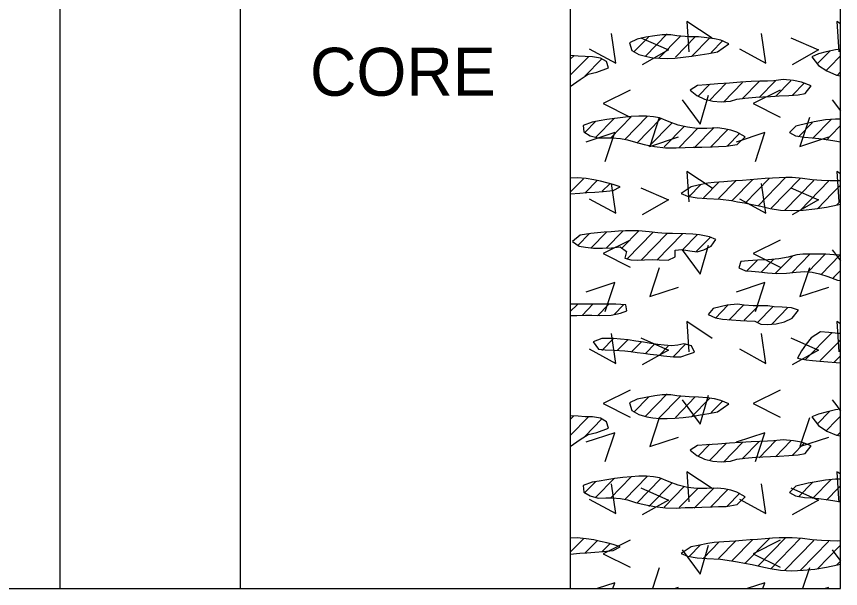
# Model space of a CAD drawing. Extents: x 0 to 0.83, y -0.65 to 1.27.
# Drawn here: x 0.719 to 0.8333, y -0.6457 to -0.5663 of the extents above; entities that cross this region are included whole.
import ezdxf

# ---------------------------------------------------------------- set-up
doc = ezdxf.new("R2010")
doc.units = 0

msp = doc.modelspace()

# ---------------------------------------------------------------- linework, layer by layer
for points in [[(0.725, 1.22083), (0.725, -0.64575)], [(0.75, 1.22083), (0.75, -0.64575)], [(0.75, 1.22083), (0.75, -0.64575)], [(0.79583, 1.22083), (0.79583, -0.64575)], [(0.725, 1.20833), (0.725, -0.64575)], [(0.83333, -0.64575), (0.83333, 1.13365)], [(0.81551, -0.56934), (0.81201, -0.56703), (0.81226, -0.57121)], [(0.83333, -0.56735), (0.83284, -0.56703), (0.83309, -0.57121)], [(0.79847, -0.57082), (0.80215, -0.57282), (0.80153, -0.5687)], [(0.80465, -0.57124), (0.80667, -0.56917)], [(0.80562, -0.56928), (0.80946, -0.57096), (0.80581, -0.57302)], [(0.80626, -0.57181), (0.80928, -0.56871)], [(0.80809, -0.57214), (0.81111, -0.56905)], [(0.81041, -0.57198), (0.81318, -0.56915)], [(0.81264, -0.5719), (0.81518, -0.5693)], [(0.8193, -0.57082), (0.82299, -0.57282), (0.82236, -0.5687)], [(0.82645, -0.56928), (0.83029, -0.57096), (0.82664, -0.57302)], [(0.81536, -0.57133), (0.81699, -0.56967)], [(0.8301, -0.57291), (0.83184, -0.57112)], [(0.7963, -0.57179), (0.79583, -0.57227)], [(0.79834, -0.57192), (0.79583, -0.57449)], [(0.79786, -0.57462), (0.80023, -0.57219)], [(0.83131, -0.57388), (0.83181, -0.57337), (0.83333, -0.5718)], [(0.83285, -0.57451), (0.83333, -0.57402)], [(0.81519, -0.57572), (0.81354, -0.57742)], [(0.81514, -0.57798), (0.81748, -0.57559)], [(0.81709, -0.5782), (0.81974, -0.57548)], [(0.8197, -0.57775), (0.82203, -0.57535)], [(0.82202, -0.57758), (0.8243, -0.57524)], [(0.82431, -0.57745), (0.82644, -0.57526)], [(0.82663, -0.57728), (0.82834, -0.57553)], [(0.80412, -0.57653), (0.80038, -0.57841), (0.80412, -0.58028)], [(0.81134, -0.57788), (0.81384, -0.58125), (0.81503, -0.57725)], [(0.82496, -0.57653), (0.82121, -0.57841), (0.82496, -0.58028)], [(0.83217, -0.57788), (0.83333, -0.57944)], [(0.79938, -0.58087), (0.79786, -0.58242)], [(0.79933, -0.58313), (0.80195, -0.58044)], [(0.80142, -0.5832), (0.8043, -0.58025)], [(0.80653, -0.58017), (0.8034, -0.58339)], [(0.80506, -0.58389), (0.8084, -0.58047)], [(0.80818, -0.58037), (0.80687, -0.58437), (0.81087, -0.58305)], [(0.82901, -0.58037), (0.8277, -0.58437), (0.8317, -0.58305)], [(0.83203, -0.58061), (0.82949, -0.58321)], [(0.80997, -0.58107), (0.80675, -0.58438)], [(0.81164, -0.58158), (0.80884, -0.58444)], [(0.81353, -0.58185), (0.81094, -0.58451)], [(0.81303, -0.58457), (0.81579, -0.58175)], [(0.81534, -0.58442), (0.81768, -0.58202)], [(0.82751, -0.58302), (0.82945, -0.58103)], [(0.83138, -0.58348), (0.83201, -0.58284), (0.83333, -0.58148)], [(0.80069, -0.58645), (0.802, -0.58245), (0.798, -0.58376)], [(0.8176, -0.58431), (0.81934, -0.58253)], [(0.82152, -0.58645), (0.82284, -0.58245), (0.81884, -0.58376)], [(0.83333, -0.5837), (0.83333, -0.58369)], [(0.79765, -0.58885), (0.79583, -0.59071)], [(0.81551, -0.59017), (0.81201, -0.58786), (0.81226, -0.59205)], [(0.82004, -0.59229), (0.82346, -0.58878)], [(0.82569, -0.5887), (0.82184, -0.59265)], [(0.82775, -0.5888), (0.8237, -0.59295)], [(0.83333, -0.58818), (0.83284, -0.58786), (0.83309, -0.59205)], [(0.7996, -0.58906), (0.79786, -0.59084)], [(0.79847, -0.59165), (0.80215, -0.59365), (0.80153, -0.58953)], [(0.8013, -0.58954), (0.80027, -0.59059)], [(0.81392, -0.5897), (0.81235, -0.5913)], [(0.8143, -0.59152), (0.8165, -0.58927)], [(0.8164, -0.59159), (0.81879, -0.58914)], [(0.81829, -0.59187), (0.82114, -0.58894)], [(0.8193, -0.59165), (0.82299, -0.59365), (0.82236, -0.58953)], [(0.82964, -0.58908), (0.82557, -0.59326)], [(0.83173, -0.58915), (0.82774, -0.59324)], [(0.83333, -0.58973), (0.83218, -0.59091), (0.83012, -0.59302)], [(0.80562, -0.59011), (0.80946, -0.59179), (0.80581, -0.59385)], [(0.82645, -0.59011), (0.83029, -0.59179), (0.82664, -0.59385)], [(0.83281, -0.59247), (0.83333, -0.59194)], [(0.79844, -0.5965), (0.79691, -0.59807)], [(0.79871, -0.59844), (0.80085, -0.59625)], [(0.80083, -0.59849), (0.80311, -0.59615)], [(0.80534, -0.59607), (0.80299, -0.59849)], [(0.80367, -0.6), (0.80732, -0.59626)], [(0.80571, -0.60012), (0.80924, -0.59651)], [(0.81142, -0.59649), (0.80785, -0.60014)], [(0.81141, -0.59871), (0.81348, -0.59659)], [(0.80412, -0.59737), (0.80038, -0.59924), (0.80412, -0.60112)], [(0.81134, -0.59871), (0.81384, -0.60208), (0.81503, -0.59808)], [(0.81528, -0.59695), (0.81331, -0.59897)], [(0.82496, -0.59737), (0.82121, -0.59924), (0.82496, -0.60112)], [(0.83217, -0.59871), (0.83235, -0.59894), (0.83333, -0.60027)], [(0.82035, -0.60163), (0.82176, -0.60018)], [(0.82233, -0.6018), (0.82408, -0.60002)], [(0.82433, -0.60198), (0.82666, -0.59959)], [(0.82909, -0.5993), (0.82656, -0.6019)], [(0.82885, -0.60177), (0.83122, -0.59934)], [(0.83325, -0.59947), (0.83065, -0.60213)], [(0.80818, -0.6012), (0.80687, -0.6052), (0.81087, -0.60389)], [(0.82901, -0.6012), (0.8277, -0.6052), (0.8317, -0.60389)], [(0.83333, -0.6016), (0.83242, -0.60253), (0.83227, -0.60269)], [(0.80069, -0.60728), (0.802, -0.60328), (0.798, -0.60459)], [(0.82152, -0.60728), (0.82284, -0.60328), (0.81884, -0.60459)], [(0.79583, -0.6073), (0.79681, -0.6063)], [(0.79898, -0.60628), (0.79747, -0.60783)], [(0.80116, -0.60627), (0.79959, -0.60787)], [(0.80328, -0.60631), (0.80188, -0.60774)], [(0.8177, -0.60641), (0.81596, -0.60819)], [(0.81988, -0.60639), (0.81785, -0.60847)], [(0.82185, -0.60658), (0.81997, -0.60851)], [(0.824, -0.60659), (0.82178, -0.60887)], [(0.82601, -0.60675), (0.82378, -0.60903)], [(0.81551, -0.61101), (0.81201, -0.60869), (0.81226, -0.61288)], [(0.83333, -0.60901), (0.83284, -0.60869), (0.83309, -0.61288)], [(0.79847, -0.61249), (0.80215, -0.61449), (0.80153, -0.61036)], [(0.8193, -0.61249), (0.82299, -0.61449), (0.82236, -0.61036)], [(0.83217, -0.61019), (0.82844, -0.61401)], [(0.80188, -0.61097), (0.8002, -0.61269)], [(0.8038, -0.61121), (0.80237, -0.61267)], [(0.80575, -0.61143), (0.80429, -0.61292)], [(0.80562, -0.61094), (0.80946, -0.61263), (0.80581, -0.61469)], [(0.80758, -0.61176), (0.80627, -0.61311)], [(0.81188, -0.61178), (0.81016, -0.61354)], [(0.82645, -0.61094), (0.83029, -0.61263), (0.82664, -0.61469)], [(0.83333, -0.61121), (0.83262, -0.61194), (0.83052, -0.61409)], [(0.80941, -0.61209), (0.80816, -0.61338)], [(0.83333, -0.61343), (0.83266, -0.61411), (0.83245, -0.61433)], [(0.80412, -0.6182), (0.80038, -0.62008), (0.80412, -0.62195)], [(0.82496, -0.6182), (0.82121, -0.62008), (0.82496, -0.62195)], [(0.80465, -0.62124), (0.80667, -0.61917)], [(0.80626, -0.62181), (0.80928, -0.61871)], [(0.80809, -0.62214), (0.81111, -0.61905)], [(0.81041, -0.62198), (0.81318, -0.61915)], [(0.81134, -0.61954), (0.81384, -0.62292), (0.81503, -0.61892)], [(0.81264, -0.6219), (0.81518, -0.6193)], [(0.81536, -0.62133), (0.81699, -0.61967)], [(0.83217, -0.61954), (0.8328, -0.62038), (0.83333, -0.6211)], [(0.7963, -0.62179), (0.79583, -0.62227)], [(0.79834, -0.62192), (0.79583, -0.62449)], [(0.80818, -0.62203), (0.80687, -0.62603), (0.81087, -0.62472)], [(0.82901, -0.62203), (0.8277, -0.62603), (0.8317, -0.62472)], [(0.8301, -0.62291), (0.83184, -0.62112)], [(0.83131, -0.62388), (0.83284, -0.62231), (0.83333, -0.6218)], [(0.79786, -0.62462), (0.80023, -0.62219)], [(0.80069, -0.62811), (0.802, -0.62411), (0.798, -0.62543)], [(0.82152, -0.62811), (0.82284, -0.62411), (0.81884, -0.62543)], [(0.83285, -0.62451), (0.83288, -0.62448), (0.83333, -0.62402)], [(0.81709, -0.6282), (0.81974, -0.62548)], [(0.8197, -0.62775), (0.82203, -0.62535)], [(0.82202, -0.62758), (0.8243, -0.62524)], [(0.82431, -0.62745), (0.82644, -0.62526)], [(0.82663, -0.62728), (0.82834, -0.62553)], [(0.81519, -0.62572), (0.81354, -0.62742)], [(0.81514, -0.62798), (0.81748, -0.62559)], [(0.81551, -0.63184), (0.81201, -0.62953), (0.81226, -0.63371)], [(0.83333, -0.62985), (0.83299, -0.62962), (0.83284, -0.62953), (0.83307, -0.63328), (0.83309, -0.63371)], [(0.79938, -0.63087), (0.79786, -0.63242)], [(0.79847, -0.63332), (0.80215, -0.63532), (0.80153, -0.6312)], [(0.79933, -0.63313), (0.80195, -0.63044)], [(0.80142, -0.6332), (0.8043, -0.63025)], [(0.80653, -0.63017), (0.8034, -0.63339)], [(0.80506, -0.63389), (0.8084, -0.63047)], [(0.80997, -0.63107), (0.80675, -0.63438)], [(0.8193, -0.63332), (0.82299, -0.63532), (0.82236, -0.6312)], [(0.82751, -0.63302), (0.82945, -0.63103)], [(0.83203, -0.63061), (0.82949, -0.63321)], [(0.80562, -0.63178), (0.80946, -0.63346), (0.80581, -0.63552)], [(0.81164, -0.63158), (0.80884, -0.63444)], [(0.81353, -0.63185), (0.81094, -0.63451)], [(0.81303, -0.63457), (0.81579, -0.63175)], [(0.81534, -0.63442), (0.81768, -0.63202)], [(0.82645, -0.63178), (0.83029, -0.63346), (0.82664, -0.63552)], [(0.83138, -0.63348), (0.83304, -0.63178), (0.83333, -0.63148)], [(0.8176, -0.63431), (0.81934, -0.63253)], [(0.83333, -0.6337), (0.83333, -0.63369)], [(0.79765, -0.63885), (0.79583, -0.64071)], [(0.7996, -0.63906), (0.79786, -0.64084)], [(0.80412, -0.63903), (0.80038, -0.64091), (0.80412, -0.64278)], [(0.8164, -0.64159), (0.81879, -0.63914)], [(0.81829, -0.64187), (0.82114, -0.63894)], [(0.82004, -0.64229), (0.82346, -0.63878)], [(0.82496, -0.63903), (0.82121, -0.64091), (0.82496, -0.64278)], [(0.82569, -0.6387), (0.82184, -0.64265)], [(0.82775, -0.6388), (0.8237, -0.64295)], [(0.82964, -0.63908), (0.82557, -0.64326)], [(0.83173, -0.63915), (0.82774, -0.64324)], [(0.8013, -0.63954), (0.80027, -0.64059)], [(0.81134, -0.64037), (0.81384, -0.64375), (0.81503, -0.63975)], [(0.81392, -0.6397), (0.81235, -0.6413)], [(0.8143, -0.64152), (0.8165, -0.63927)], [(0.83333, -0.63973), (0.83321, -0.63985), (0.83012, -0.64302)], [(0.83217, -0.64037), (0.83325, -0.64182), (0.83333, -0.64194)], [(0.83281, -0.64247), (0.83325, -0.64202), (0.83333, -0.64194)], [(0.80818, -0.64287), (0.80723, -0.64575)], [(0.82901, -0.64287), (0.82807, -0.64575)], [(0.80174, -0.64575), (0.802, -0.64495), (0.79956, -0.64575)], [(0.82257, -0.64575), (0.82284, -0.64495), (0.82039, -0.64575)], [(0.70417, -0.64575), (0.725, -0.64575)], [(0.725, -0.64575), (0.75, -0.64575)], [(0.75, -0.64575), (0.79583, -0.64575)], [(0.79583, -0.64575), (0.83333, -0.64575)], [(0.79583, -0.64575), (0.83333, -0.64575)], [(0.81027, -0.64575), (0.81087, -0.64555)], [(0.83111, -0.64575), (0.8317, -0.64555)]]:
    msp.add_lwpolyline(points)
for points in [[(0.81233, -0.56913), (0.81063, -0.56901), (0.80977, -0.56887), (0.8086, -0.56887), (0.80755, -0.56901), (0.80632, -0.56921), (0.80513, -0.56945), (0.80403, -0.56998), (0.80436, -0.57104), (0.80536, -0.5716), (0.80647, -0.5719), (0.8073, -0.57205), (0.80824, -0.57213), (0.80926, -0.57214), (0.81035, -0.57209), (0.81149, -0.57198), (0.81267, -0.57184), (0.81386, -0.57165), (0.81506, -0.57144), (0.81625, -0.57121), (0.81783, -0.57012), (0.81673, -0.56963), (0.81585, -0.56942), (0.8148, -0.56927), (0.81361, -0.56916)], [(0.79583, -0.57604), (0.79719, -0.57505), (0.79831, -0.57434), (0.79951, -0.57407), (0.80111, -0.57347), (0.80086, -0.57259), (0.80002, -0.57211), (0.79889, -0.57192), (0.79791, -0.57189), (0.79694, -0.57183), (0.79583, -0.57175)], [(0.83265, -0.57094), (0.83136, -0.57125), (0.83028, -0.57152), (0.82934, -0.57192), (0.83026, -0.57312), (0.83142, -0.57388), (0.83279, -0.57446), (0.83333, -0.57456), (0.83333, -0.57085)], [(0.82537, -0.57509), (0.82408, -0.57524), (0.82319, -0.5753), (0.82214, -0.57532), (0.82091, -0.57536), (0.81947, -0.57545), (0.81792, -0.57557), (0.81632, -0.57569), (0.81475, -0.57579), (0.81348, -0.57589), (0.81247, -0.57653), (0.81337, -0.57729), (0.81444, -0.57779), (0.81561, -0.57808), (0.81675, -0.57818), (0.81807, -0.57807), (0.81896, -0.5778), (0.82003, -0.57765), (0.82157, -0.57753), (0.82253, -0.57747), (0.82362, -0.57741), (0.82483, -0.57735), (0.82618, -0.57729), (0.82745, -0.57718), (0.82842, -0.577), (0.82927, -0.57595), (0.82791, -0.57543), (0.82679, -0.57523)], [(0.79885, -0.581), (0.79763, -0.58146), (0.79773, -0.58236), (0.79859, -0.58288), (0.7997, -0.58318), (0.80074, -0.58317), (0.80165, -0.58315), (0.80281, -0.58324), (0.80377, -0.58344), (0.80486, -0.58379), (0.80606, -0.58409), (0.80751, -0.58437), (0.80905, -0.58455), (0.81052, -0.58458), (0.81177, -0.58452), (0.81289, -0.58448), (0.81408, -0.58445), (0.81553, -0.58441), (0.81642, -0.58438), (0.81745, -0.58435), (0.81897, -0.58408), (0.82011, -0.58304), (0.81896, -0.58237), (0.8181, -0.5821), (0.81717, -0.58191), (0.81626, -0.5818), (0.81479, -0.58186), (0.81343, -0.58186), (0.8121, -0.58171), (0.8108, -0.58141), (0.80953, -0.58095), (0.8082, -0.5804), (0.80736, -0.58024), (0.8064, -0.58016), (0.80536, -0.58016), (0.80427, -0.58022), (0.80314, -0.58033), (0.80201, -0.58048), (0.8009, -0.58064), (0.79984, -0.58082)], [(0.83263, -0.58056), (0.83126, -0.58069), (0.82969, -0.58096), (0.82883, -0.58113), (0.82712, -0.58154), (0.82623, -0.58241), (0.82708, -0.5829), (0.82831, -0.58309), (0.82941, -0.58315), (0.83033, -0.58324), (0.83165, -0.58343), (0.83253, -0.58357), (0.83333, -0.58371), (0.83333, -0.58056)], [(0.79583, -0.59096), (0.79715, -0.59085), (0.79814, -0.59078), (0.79922, -0.5907), (0.80039, -0.59061), (0.80179, -0.59049), (0.80275, -0.58998), (0.80179, -0.58963), (0.80091, -0.58942), (0.80003, -0.5892), (0.79909, -0.58899), (0.79803, -0.58883), (0.79677, -0.58873), (0.79583, -0.58875)], [(0.82816, -0.59321), (0.82978, -0.59304), (0.83137, -0.59278), (0.8329, -0.59247), (0.83333, -0.59237), (0.83333, -0.58913), (0.83295, -0.58916), (0.83188, -0.58914), (0.83071, -0.58909), (0.82938, -0.58898), (0.82807, -0.58882), (0.82662, -0.5887), (0.82576, -0.58869), (0.82484, -0.58872), (0.82387, -0.58877), (0.82286, -0.58884), (0.82182, -0.58892), (0.82077, -0.589), (0.81973, -0.58909), (0.81872, -0.58916), (0.81715, -0.58926), (0.81579, -0.58935), (0.81491, -0.58948), (0.81357, -0.58976), (0.8126, -0.58997), (0.81121, -0.59089), (0.8121, -0.59125), (0.81345, -0.5915), (0.81479, -0.59159), (0.81668, -0.59169), (0.81818, -0.59189), (0.81905, -0.59204), (0.82, -0.59221), (0.82107, -0.59243), (0.82225, -0.59268), (0.82357, -0.59297), (0.82501, -0.5932), (0.82656, -0.59327)], [(0.79708, -0.59819), (0.79794, -0.59837), (0.79904, -0.59848), (0.80028, -0.59851), (0.80156, -0.59846), (0.80274, -0.5983), (0.80361, -0.59896), (0.80338, -0.59986), (0.80422, -0.60013), (0.80517, -0.60015), (0.80613, -0.6001), (0.8072, -0.60006), (0.80818, -0.6001), (0.80939, -0.60017), (0.81037, -0.5997), (0.81038, -0.59876), (0.8113, -0.59869), (0.81244, -0.59888), (0.81346, -0.59899), (0.81438, -0.59873), (0.81539, -0.59819), (0.81601, -0.59728), (0.81517, -0.5969), (0.81374, -0.59663), (0.81285, -0.59653), (0.81187, -0.59648), (0.81, -0.59647), (0.8091, -0.59646), (0.808, -0.59638), (0.80678, -0.59622), (0.8053, -0.59609), (0.80443, -0.59608), (0.80349, -0.5961), (0.80251, -0.59614), (0.80152, -0.5962), (0.80054, -0.59628), (0.79959, -0.59637), (0.7987, -0.59647), (0.79722, -0.59669), (0.79614, -0.59757)], [(0.83241, -0.59941), (0.83129, -0.59934), (0.83017, -0.59931), (0.8291, -0.5993), (0.82811, -0.59934), (0.82728, -0.59943), (0.82608, -0.59973), (0.82476, -0.59996), (0.8233, -0.60009), (0.82183, -0.60017), (0.82051, -0.60023), (0.81951, -0.60033), (0.81922, -0.6012), (0.82013, -0.60162), (0.82097, -0.60167), (0.822, -0.60177), (0.82318, -0.6019), (0.82448, -0.60199), (0.82584, -0.60196), (0.82719, -0.6018), (0.82836, -0.60173), (0.8294, -0.60181), (0.83043, -0.60204), (0.83156, -0.60243), (0.83291, -0.60292), (0.83333, -0.603), (0.83333, -0.59948)], [(0.79583, -0.60782), (0.79676, -0.60783), (0.79792, -0.60781), (0.79882, -0.60777), (0.79992, -0.60782), (0.80151, -0.60777), (0.80282, -0.60751), (0.80367, -0.60719), (0.80354, -0.60636), (0.80216, -0.60627), (0.79583, -0.60627)], [(0.81822, -0.60846), (0.81944, -0.60852), (0.82033, -0.60856), (0.82145, -0.60863), (0.82229, -0.60905), (0.82324, -0.60909), (0.82438, -0.60898), (0.82555, -0.6087), (0.82662, -0.60819), (0.82749, -0.60709), (0.82651, -0.60679), (0.82524, -0.60669), (0.82413, -0.60663), (0.82324, -0.60652), (0.82226, -0.6065), (0.82121, -0.60648), (0.81995, -0.60639), (0.81902, -0.60627), (0.81761, -0.60641), (0.81566, -0.60685), (0.81496, -0.60769), (0.81598, -0.60818), (0.81695, -0.60836)], [(0.83305, -0.61032), (0.83171, -0.61021), (0.83054, -0.61011), (0.82925, -0.61093), (0.82857, -0.61184), (0.82792, -0.61273), (0.82735, -0.61375), (0.82858, -0.61398), (0.82945, -0.61408), (0.83045, -0.61418), (0.83155, -0.61427), (0.83272, -0.61437), (0.83333, -0.61442), (0.83333, -0.61033)], [(0.80066, -0.61262), (0.80188, -0.61263), (0.80339, -0.61276), (0.80423, -0.61285), (0.8051, -0.61296), (0.806, -0.61308), (0.80692, -0.6132), (0.80784, -0.61332), (0.80875, -0.61343), (0.81014, -0.61357), (0.81119, -0.61356), (0.81222, -0.61322), (0.81308, -0.61293), (0.81267, -0.61203), (0.8116, -0.61178), (0.81075, -0.61198), (0.80989, -0.61206), (0.80885, -0.61198), (0.80799, -0.61187), (0.80703, -0.61173), (0.806, -0.61156), (0.80492, -0.61139), (0.80384, -0.61124), (0.8028, -0.61111), (0.80182, -0.61101), (0.8002, -0.61101), (0.79901, -0.61148), (0.79974, -0.61252)], [(0.81233, -0.61913), (0.81063, -0.61901), (0.80977, -0.61887), (0.8086, -0.61887), (0.80755, -0.61901), (0.80632, -0.61921), (0.80513, -0.61945), (0.80403, -0.61998), (0.80436, -0.62104), (0.80536, -0.6216), (0.80647, -0.6219), (0.8073, -0.62205), (0.80824, -0.62213), (0.80926, -0.62214), (0.81035, -0.62209), (0.81149, -0.62198), (0.81267, -0.62184), (0.81386, -0.62165), (0.81506, -0.62144), (0.81625, -0.62121), (0.81783, -0.62012), (0.81673, -0.61963), (0.81585, -0.61942), (0.8148, -0.61927), (0.81361, -0.61916)], [(0.83265, -0.62094), (0.83136, -0.62125), (0.83028, -0.62152), (0.82934, -0.62192), (0.83026, -0.62312), (0.83142, -0.62388), (0.83279, -0.62446), (0.83333, -0.62456), (0.83333, -0.62085)], [(0.79583, -0.62604), (0.79719, -0.62505), (0.79831, -0.62434), (0.79951, -0.62407), (0.80111, -0.62347), (0.80086, -0.62259), (0.80002, -0.62211), (0.79889, -0.62192), (0.79791, -0.62189), (0.79694, -0.62183), (0.79583, -0.62175)], [(0.82537, -0.62509), (0.82408, -0.62524), (0.82319, -0.6253), (0.82214, -0.62532), (0.82091, -0.62536), (0.81947, -0.62545), (0.81792, -0.62557), (0.81632, -0.62569), (0.81475, -0.62579), (0.81348, -0.62589), (0.81247, -0.62653), (0.81337, -0.62729), (0.81444, -0.62779), (0.81561, -0.62808), (0.81675, -0.62818), (0.81807, -0.62807), (0.81896, -0.6278), (0.82003, -0.62765), (0.82157, -0.62753), (0.82253, -0.62747), (0.82362, -0.62741), (0.82483, -0.62735), (0.82618, -0.62729), (0.82745, -0.62718), (0.82842, -0.627), (0.82927, -0.62595), (0.82791, -0.62543), (0.82679, -0.62523)], [(0.79885, -0.631), (0.79763, -0.63146), (0.79773, -0.63236), (0.79859, -0.63288), (0.7997, -0.63318), (0.80074, -0.63317), (0.80165, -0.63315), (0.80281, -0.63324), (0.80377, -0.63344), (0.80486, -0.63379), (0.80606, -0.63409), (0.80751, -0.63436), (0.80905, -0.63455), (0.81052, -0.63458), (0.81177, -0.63452), (0.81289, -0.63448), (0.81408, -0.63445), (0.81553, -0.63441), (0.81642, -0.63438), (0.81745, -0.63435), (0.81897, -0.63408), (0.82011, -0.63304), (0.81896, -0.63237), (0.8181, -0.6321), (0.81717, -0.63191), (0.81626, -0.6318), (0.81479, -0.63186), (0.81343, -0.63186), (0.8121, -0.63171), (0.8108, -0.63141), (0.80953, -0.63095), (0.8082, -0.6304), (0.80736, -0.63024), (0.8064, -0.63016), (0.80536, -0.63016), (0.80427, -0.63022), (0.80314, -0.63033), (0.80201, -0.63048), (0.8009, -0.63064), (0.79984, -0.63082)], [(0.83263, -0.63056), (0.83126, -0.63069), (0.82969, -0.63096), (0.82883, -0.63113), (0.82712, -0.63154), (0.82623, -0.63241), (0.82708, -0.6329), (0.82831, -0.63309), (0.82941, -0.63315), (0.83033, -0.63324), (0.83165, -0.63343), (0.83253, -0.63357), (0.83333, -0.63371), (0.83333, -0.63056)], [(0.79583, -0.64096), (0.79715, -0.64085), (0.79814, -0.64078), (0.79922, -0.6407), (0.80039, -0.64061), (0.80179, -0.64049), (0.80275, -0.63998), (0.80179, -0.63963), (0.80091, -0.63942), (0.80003, -0.6392), (0.79909, -0.63899), (0.79803, -0.63883), (0.79677, -0.63873), (0.79583, -0.63875)], [(0.82816, -0.64321), (0.82978, -0.64304), (0.83137, -0.64278), (0.8329, -0.64247), (0.83333, -0.64237), (0.83333, -0.63913), (0.83295, -0.63916), (0.83188, -0.63914), (0.83071, -0.63909), (0.82938, -0.63898), (0.82807, -0.63882), (0.82662, -0.6387), (0.82576, -0.63869), (0.82484, -0.63872), (0.82387, -0.63877), (0.82286, -0.63884), (0.82182, -0.63892), (0.82077, -0.639), (0.81973, -0.63909), (0.81872, -0.63916), (0.81715, -0.63926), (0.81579, -0.63935), (0.81491, -0.63948), (0.81357, -0.63976), (0.8126, -0.63997), (0.81121, -0.64089), (0.8121, -0.64125), (0.81345, -0.6415), (0.81479, -0.64159), (0.81668, -0.64169), (0.81818, -0.64189), (0.81905, -0.64204), (0.82, -0.64221), (0.82107, -0.64243), (0.82225, -0.64268), (0.82357, -0.64297), (0.82501, -0.6432), (0.82656, -0.64327)]]:
    msp.add_lwpolyline(points, close=True)

# ---------------------------------------------------------------- texts
msp.add_text('CORE', height=0.006667).set_placement((0.75971, -0.57733))

doc.saveas('drawing.dxf')
